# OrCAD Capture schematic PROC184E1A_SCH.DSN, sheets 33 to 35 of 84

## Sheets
33 37. SERDES CLOCK GENERATOR #2: size C; title: SERDES CLOCK GENERATOR #2; note: PROC184_SCH
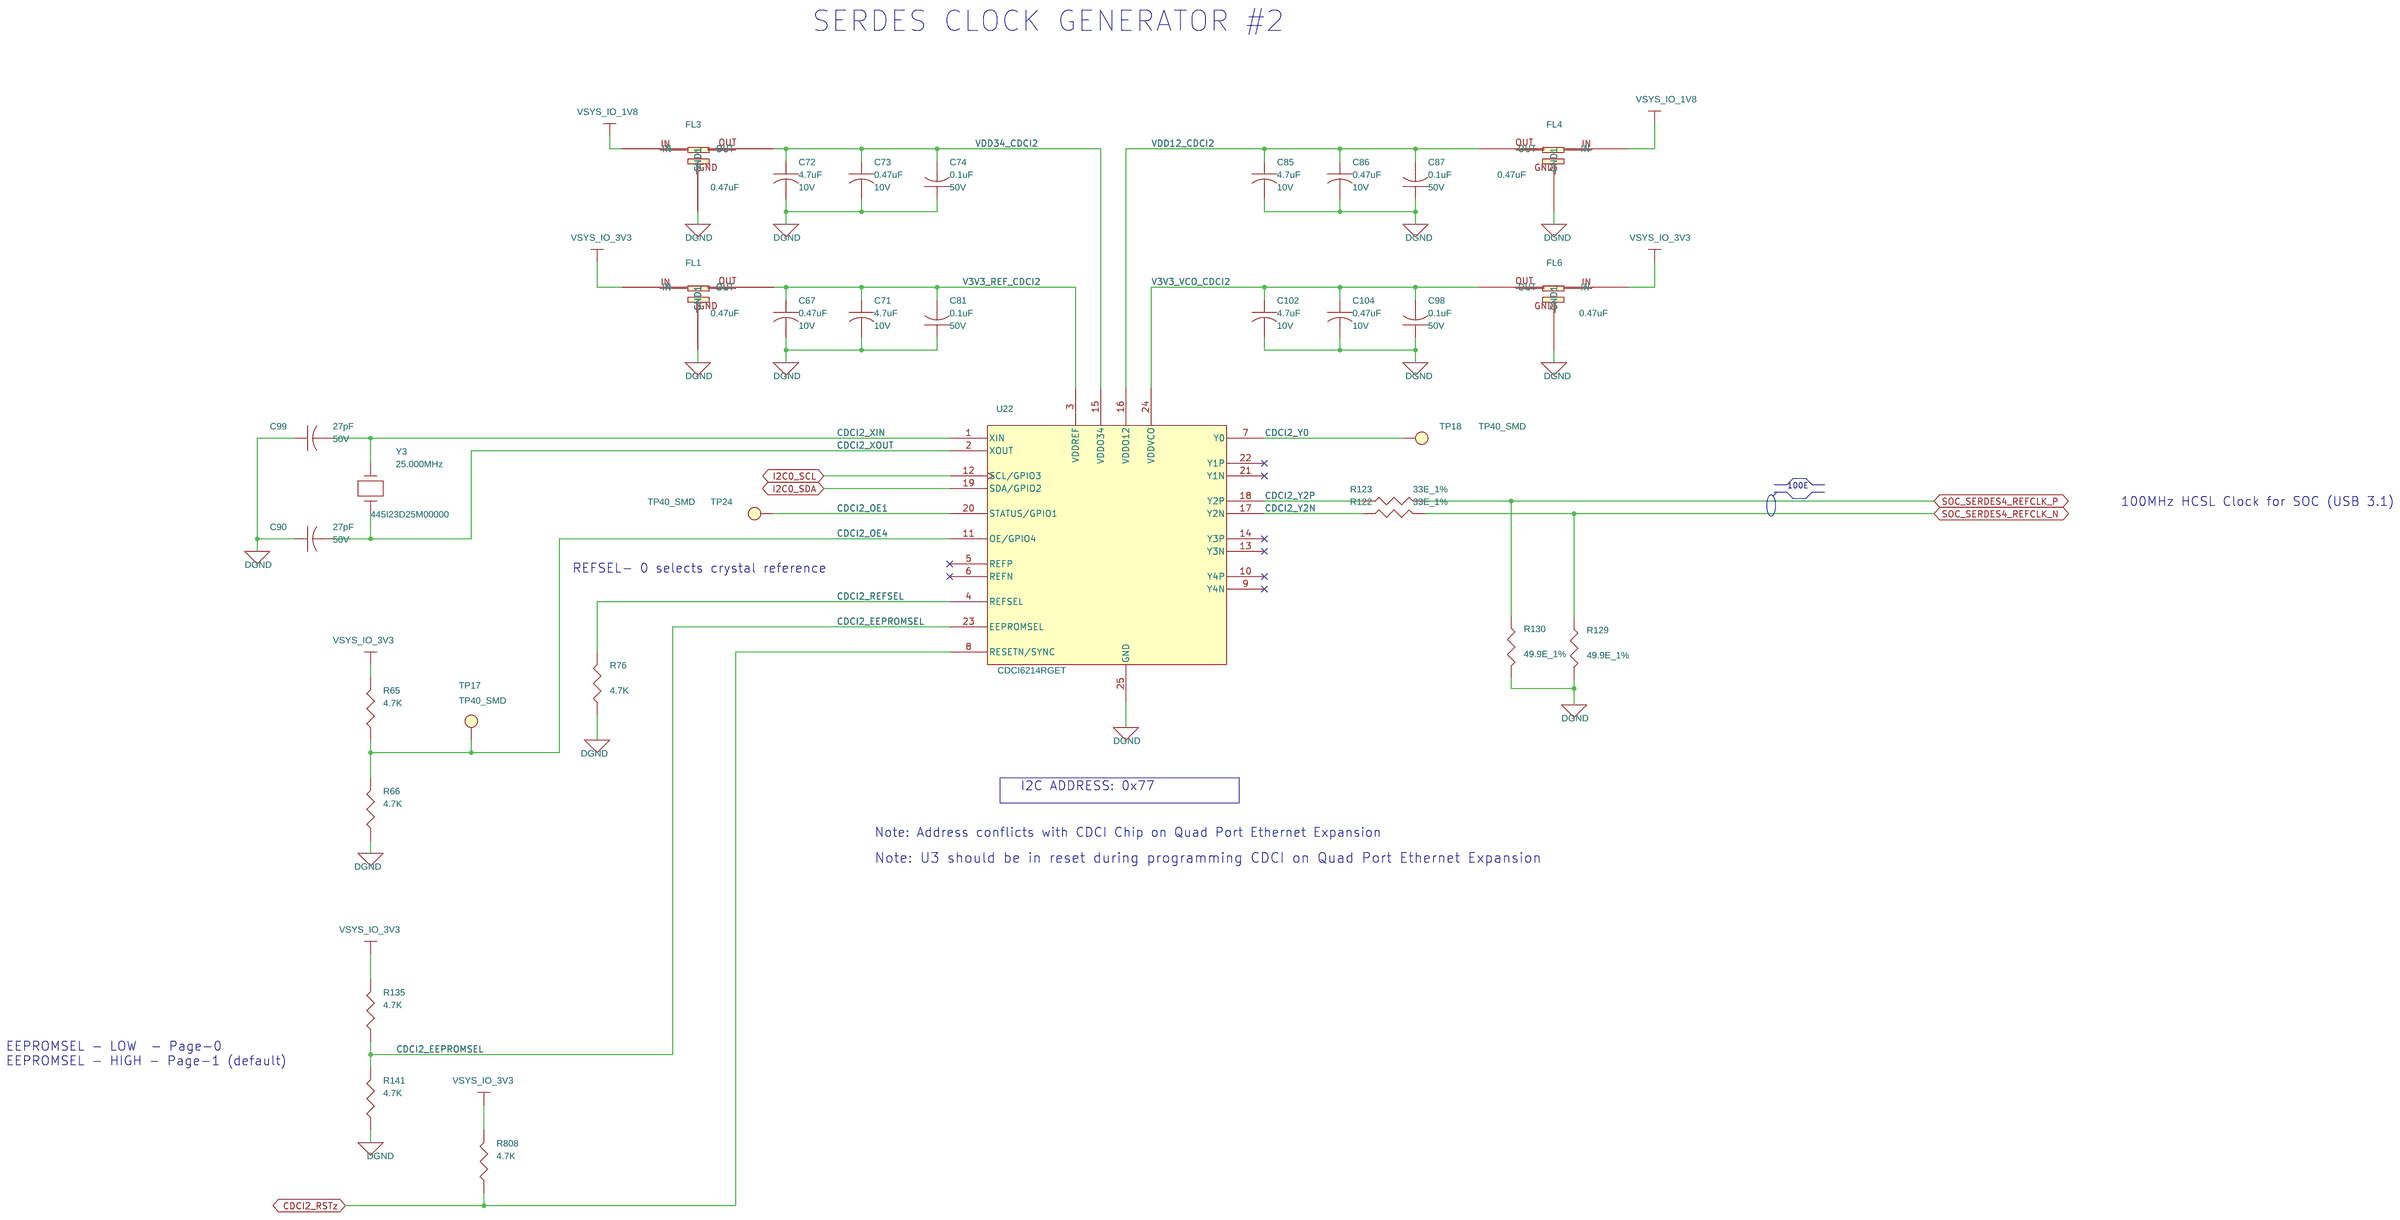
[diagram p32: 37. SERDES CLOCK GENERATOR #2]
34 38. PERIPHERAL CLOCK GENERATOR: size C; title: PERIPHERAL CLOCK GENERATOR; note: PROC184_SCH
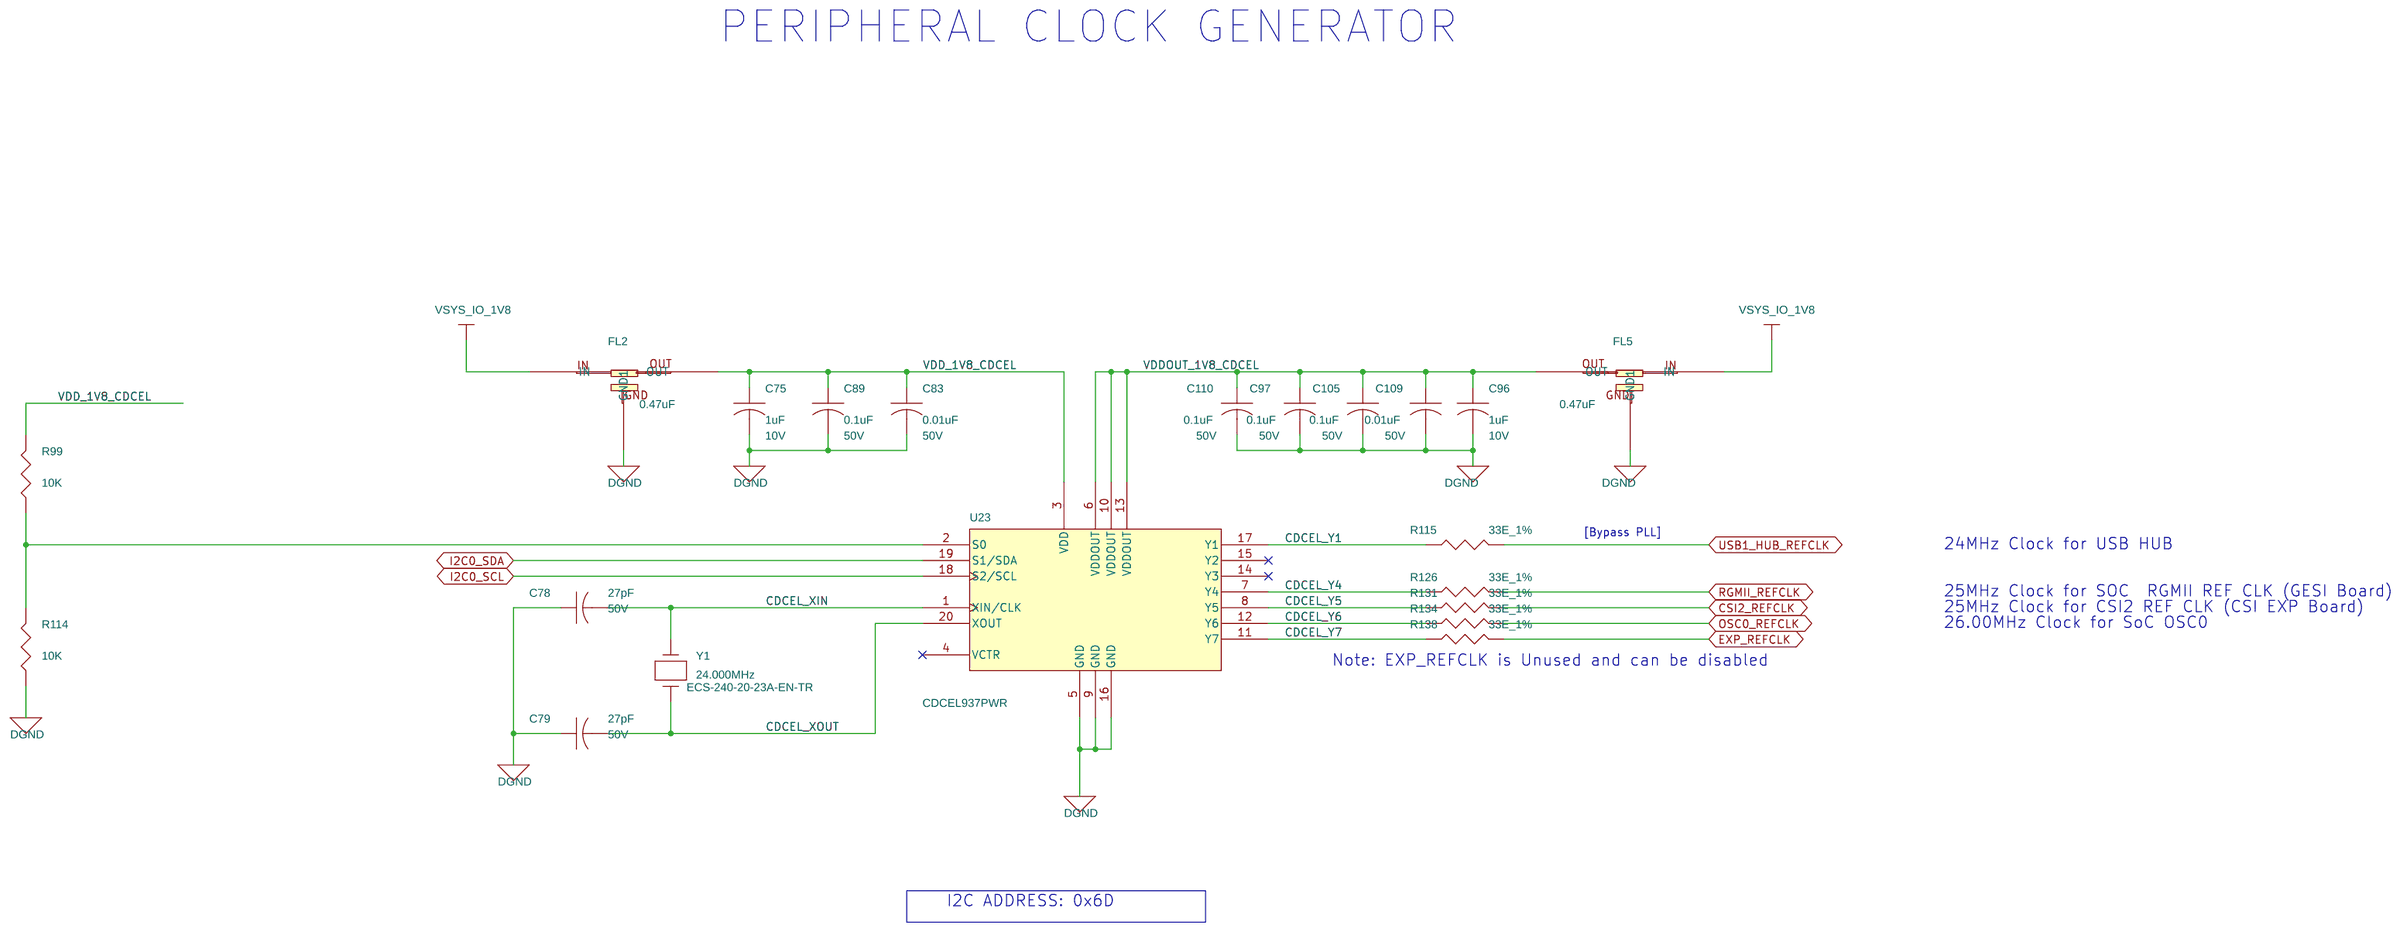
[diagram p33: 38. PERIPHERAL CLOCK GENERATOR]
35 39. RESET BUTTONs: size C; title: RESET BUTTONs; note: PROC184_SCH
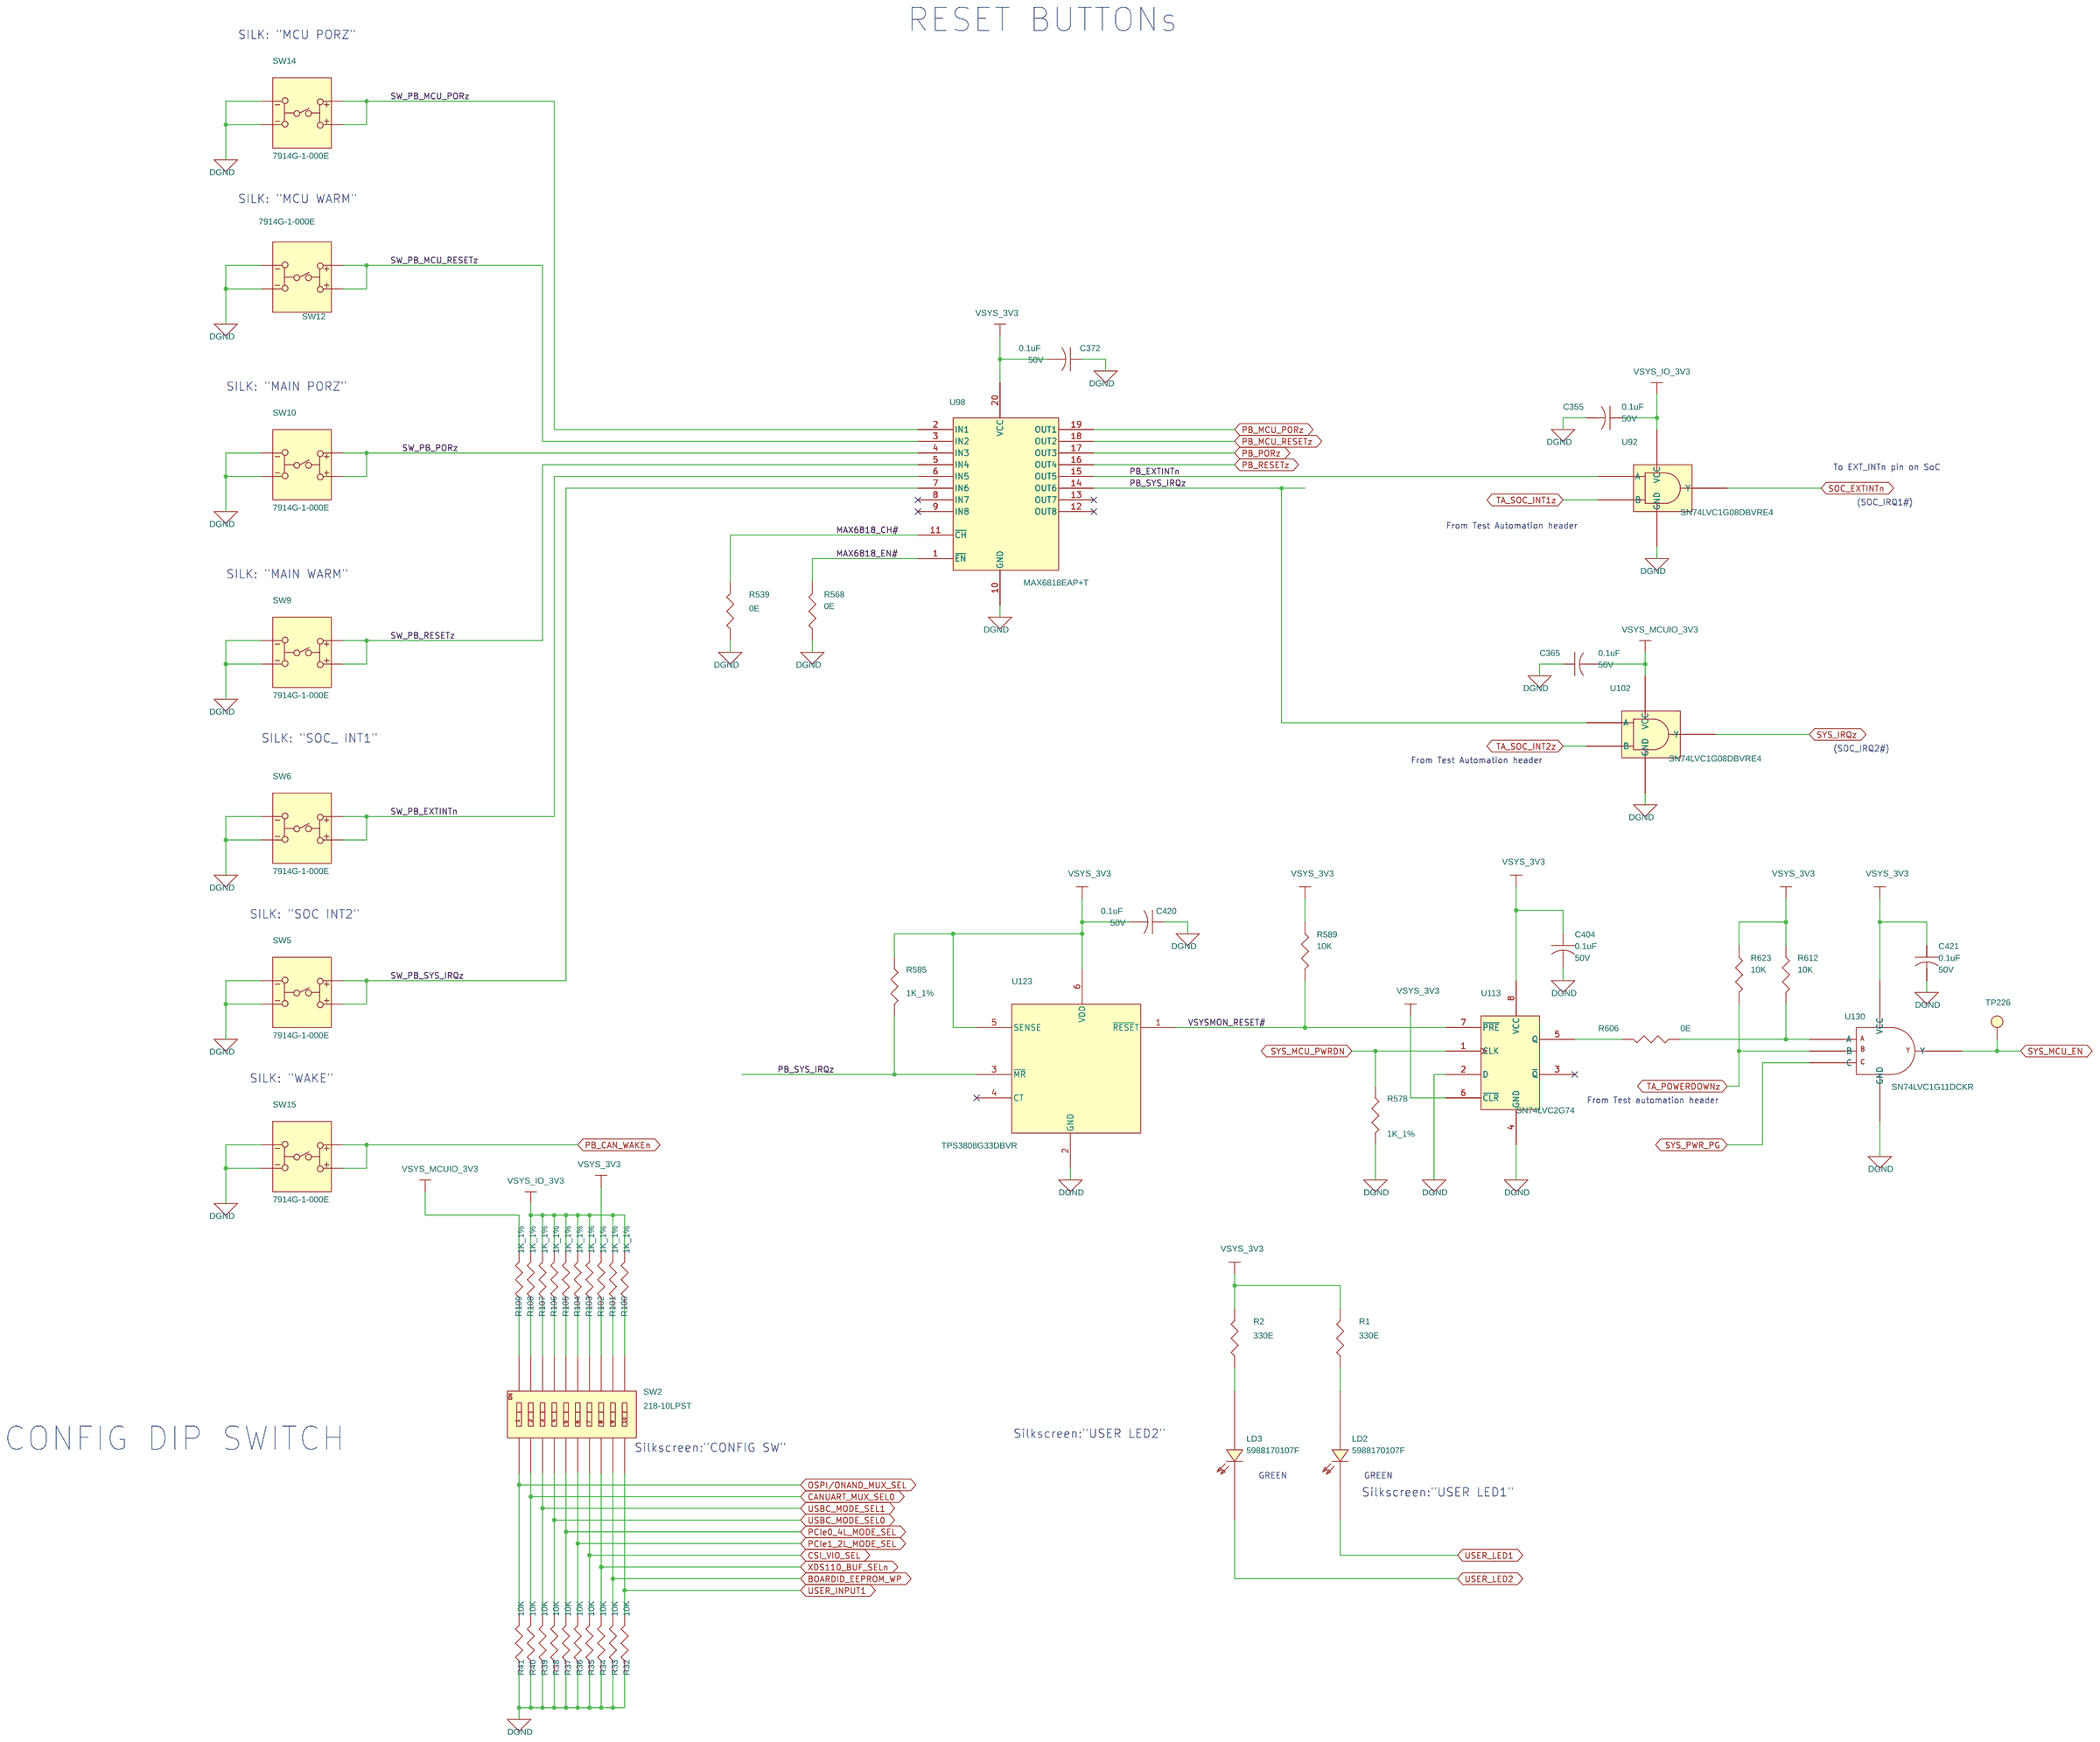
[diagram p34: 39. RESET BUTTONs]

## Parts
sheet 37. SERDES CLOCK GENERATOR #2
C67  0.47uF  [CAP0402_0-75]
C71  4.7uF  [CAP0402_0-75]
C72  4.7uF  [CAP0402_0-75]
C73  0.47uF  [CAP0402_0-75]
C74  0.1uF  [CAP0402_0-75]
C81  0.1uF  [CAP0402_0-75]
C85  4.7uF  [CAP0402_0-75]
C86  0.47uF  [CAP0402_0-75]
C87  0.1uF  [CAP0402_0-75]
C90  27pF  [CAP0402_0-75]
C98  0.1uF  [CAP0402_0-75]
C99  27pF  [CAP0402_0-75]
C102  4.7uF  [CAP0402_0-75]
C104  0.47uF  [CAP0402_0-75]
FL1  0.47uF  [EMIFIL_NFM21P_0805]
FL3  0.47uF  [EMIFIL_NFM21P_0805]
FL4  0.47uF  [EMIFIL_NFM21P_0805]
FL6  0.47uF  [EMIFIL_NFM21P_0805]
R65  4.7K  [RES0402_0-5]
R66  4.7K  [RES0402_0-5]
R76  4.7K  [RES0402_0-5]
R122  33E_1%  [RES0402_0-5]
R123  33E_1%  [RES0402_0-5]
R129  49.9E_1%  [RES0402_0-5]
R130  49.9E_1%  [RES0402_0-5]
R135  4.7K  [RES0402_0-5]
R141  4.7K  [RES0402_0-5]
R808  4.7K  [RES0402_0-5]
TP17  TP40_SMD  [TP40_SMD]
TP18  TP40_SMD  [TP40_SMD]
TP24  TP40_SMD  [TP40_SMD]
U22  CDCI6214RGET  [QFN24_19-68_160X160_1]
Y3  25.000MHz  [XTAL_ABM3_205X130_SMD_1-4]
sheet 38. PERIPHERAL CLOCK GENERATOR
C75  1uF  [CAP0402_0-75]
C78  27pF  [CAP0402_0-75]
C79  27pF  [CAP0402_0-75]
C83  0.01uF  [CAP0402_0-75]
C89  0.1uF  [CAP0402_0-75]
C96  1uF  [CAP0402_0-75]
C97  0.1uF  [CAP0402_0-75]
C105  0.1uF  [CAP0402_0-75]
C109  0.01uF  [CAP0402_0-75]
C110  0.1uF  [CAP0402_0-75]
FL2  0.47uF  [EMIFIL_NFM21P_0805]
FL5  0.47uF  [EMIFIL_NFM21P_0805]
R99  10K  [RES0402_0-5]
R114  10K  [RES0402_0-5]
R115  33E_1%  [RES0402_0-5]
R126  33E_1%  [RES0402_0-5]
R131  33E_1%  [RES0402_0-5]
R134  33E_1%  [RES0402_0-5]
R138  33E_1%  [RES0402_0-5]
U23  CDCEL937PWR  [TSSOP20_25-59_260X180_1-2]
Y1  24.000MHz  [XTAL_ECX-64AEN_240X150_SMD_1-1]
sheet 39. RESET BUTTONs
C355  0.1uF  [CAP0402_0-75]
C365  0.1uF  [CAP0402_0-75]
C372  0.1uF  [CAP0402_0-75]
C404  0.1uF  [CAP0402_0-75]
C420  0.1uF  [CAP0402_0-75]
C421  0.1uF  [CAP0402_0-75]
LD2  5988170107F  [LED_0805_0-7]
LD3  5988170107F  [LED_0805_0-7]
R1  330E  [RES0402_0-5]
R2  330E  [RES0402_0-5]
R32  10K  [RES0402_0-5]
R33  10K  [RES0402_0-5]
R34  10K  [RES0402_0-5]
R35  10K  [RES0402_0-5]
R36  10K  [RES0402_0-5]
R37  10K  [RES0402_0-5]
R38  10K  [RES0402_0-5]
R39  10K  [RES0402_0-5]
R40  10K  [RES0402_0-5]
R41  10K  [RES0402_0-5]
R100  1K_1%  [RES0402_0-5]
R101  1K_1%  [RES0402_0-5]
R102  1K_1%  [RES0402_0-5]
R103  1K_1%  [RES0402_0-5]
R104  1K_1%  [RES0402_0-5]
R105  1K_1%  [RES0402_0-5]
R106  1K_1%  [RES0402_0-5]
R107  1K_1%  [RES0402_0-5]
R108  1K_1%  [RES0402_0-5]
R109  1K_1%  [RES0402_0-5]
R539  0E  [RES0402_0-5]
R568  0E  [RES0402_0-5]
R578  1K_1%  [RES0402_0-5]
R585  1K_1%  [RES0402_0-5]
R589  10K  [RES0402_0-5]
R606  0E  [RES0402_0-5]
R612  10K  [RES0402_0-5]
R623  10K  [RES0402_0-5]
SW2  218-10LPST  [SW10_50_550X230_SMD]
SW5  7914G-1-000E  [SW4_100X216_200X200_SMD_4-2]
SW6  7914G-1-000E  [SW4_100X216_200X200_SMD_4-2]
SW9  7914G-1-000E  [SW4_100X216_200X200_SMD_4-2]
SW10  7914G-1-000E  [SW4_100X216_200X200_SMD_4-2]
SW12  7914G-1-000E  [SW4_100X216_200X200_SMD_4-2]
SW14  7914G-1-000E  [SW4_100X216_200X200_SMD_4-2]
SW15  7914G-1-000E  [SW4_100X216_200X200_SMD_4-2]
TP226  TP40_SMD  [TP40_SMD]
U92  SN74LVC1G08DBVRE4  [SOT23-5]
U98  MAX6818EAP+T  [SSOP20_25-59_295X220_2]
U102  SN74LVC1G08DBVRE4  [SOT23-5]
U113  SN74LVC2G74  [VSSOP8_19-68_85X95]
U123  TPS3808G33DBVR  [SOT23-6_1-5]
U130  SN74LVC1G11DCKR  [SC70-6]

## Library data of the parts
C67 C73 C86 C104 = CAP: CAP CERAMIC 0.47uF 10V 10% X7S AUTO 0402; Automotive Alternate_mfr_name: MURATA; Automotive Alternate_mfr_part_number: GCM155C71A474KE36D; Chkd/date: MANIRAJA/280918; Crtd /date: ALVY/280918; Custom_Duty: 15%; Customs_HS_Code: 85322990; Direct Alternate_mfr_name: MURATA; Direct Alternate_mfr_part_number: GCM155C71A474KE36D; Distributor_name: DIGIKEY; Distributor_part_number: 490-14427-1-ND; Footprint Path: Y:\MIS_DATABASE\Library\ALTIUM_TOOL\PCB_FOOTPRINTS\Altium_Footprint_Lib.PcbLib; Height: 0.60MM; Library Path: Y:\MIS_DATABASE\Library\ALTIUM_TOOL\SCHEMATICS_PARTS\MS_DISCRETE_Library.schlib; Manufacturer: MURATA; Mfr_name: MURATA; Mfr_part_number: GCM155C71A474KE36D; Mistral Part No: 120018090057-R; Package: 0402; Part_type: CAPACITORS\CERAMIC; Project: TI_J7_SVB-DUT; RoHS: RoHS; Temperature: -55°C+125°C; Tolerance: 10%; Voltage: 10V; Wattage: NA; Weight: 6mg; Datasheet: Y:\MIS_DATABASE\DATASHEETS\CAPACITORS\GCM155C71A474KE36D.PDF
C71 C72 C85 C102 = CAP: CAP CERAMIC 4.7uF 10V 20% X5R 0402; Automotive Alternate_mfr_name: MURATA; Automotive Alternate_mfr_part_number: GRT155R61A475ME13D; Chkd/date: VASANTHA/061216; Crtd /date: CHAITHANYA/070612; Custom_Duty: 15%; Customs_HS_Code: 85322990; Direct Alternate_mfr_name: MURATA; Direct Alternate_mfr_part_number: GRM155R61A475MEAAD; Distributor_name: DIGIKEY; Distributor_part_number: 445-8023-1-ND; Footprint Path: Y:\MIS_DATABASE\Library\ALTIUM_TOOL\PCB_FOOTPRINTS\Altium_Footprint_Lib.PcbLib; Height: 0.55MM; Library Path: Y:\MIS_DATABASE\Library\ALTIUM_TOOL\SCHEMATICS_PARTS\MS_DISCRETE_Library.schlib; Manufacturer: TDK CORPORATION; Mfr_name: TDK CORPORATION; Mfr_part_number: C1005X5R1A475M; Mistral Part No: 120012060002-R; Package: 0402; Part_type: CAPACITORS\CERAMIC; Project: IRIS; RoHS: RoHS; Temperature: -55°C+85°C; Tolerance: 20%; Voltage: 10V; Wattage: NA; Weight: 0.65mg; Datasheet: Y:\MIS_DATABASE\DATASHEETS\CAPACITORS\TDK-C-SER_JUL17.PDF
C74 C81 C87 C89 C97 C98 C105 C110 C355 C365 C372 C404 C420 C421 = CAP: CAP CERAMIC 0.1uF 50V 10% X7R 0402; Automotive Alternate_mfr_name: TDK; Automotive Alternate_mfr_part_number: CGA2B3X7R1H104K050BB; Chkd/date: MANIRAJA/261020; Crtd /date: ALVY/211020; Custom_Duty: 15%; Customs_HS_Code: 85322990; Direct Alternate_mfr_name: TDK; Direct Alternate_mfr_part_number: C1005X7R1H104K050BE; Distributor_name: DIGIKEY; Distributor_part_number: 490-10700-1-ND; Footprint Path: Y:\MIS_DATABASE\Library\ALTIUM_TOOL\PCB_FOOTPRINTS\Altium_Footprint_Lib.PcbLib; Height: 0.55MM; Library Path: Y:\MIS_DATABASE\Library\ALTIUM_TOOL\SCHEMATICS_PARTS\MS_DISCRETE_Library.schlib; Manufacturer: MURATA; Mfr_name: MURATA; Mfr_part_number: GRM155R71H104KE14D; Mistral Part No: 120011100014-R; Package: 0402; Part_type: CAPACITORS\CERAMIC; Project: J7_CP; RoHS: RoHS; Temperature: -55°C+125°C; Tolerance: 10%; Voltage: 50V; Wattage: NA; Weight: 3.1mg; Datasheet: Y:\MIS_DATABASE\DATASHEETS\CAPACITORS\GRM155R71H104KE14.PDF
C90 C99 = CAP: CAP CERAMIC 27pF 50V 5% C0G(NP0) 0402; Assembly_Instruction: DNI; Automotive Alternate_mfr_name: TDK; Automotive Alternate_mfr_part_number: CGA2B2C0G1H270J050BA; Chkd/date: MAZHAR/241208; Crtd /date: GEETHA/090606; Custom_Duty: 15%; Customs_HS_Code: 85322990; Direct Alternate_mfr_name: SAMSUNG; Direct Alternate_mfr_part_number: CL05C270JB5NNNC; Distributor_name: DIGIKEY; Distributor_part_number: 311-1019-1-ND; Footprint Path: Y:\MIS_DATABASE\Library\ALTIUM_TOOL\PCB_FOOTPRINTS\Altium_Footprint_Lib.PcbLib; Height: 0.55MM; Library Path: Y:\MIS_DATABASE\Library\ALTIUM_TOOL\SCHEMATICS_PARTS\MS_DISCRETE_Library.schlib; Manufacturer: YAGEO AMERICA; Mfr_name: YAGEO AMERICA; Mfr_part_number: CC0402JRNPO9BN270; Mistral Part No: 120014100024-R; Package: 0402; Part_type: CAPACITORS\CERAMIC; Project: PNAV; RoHS: RoHS; Temperature: -55°C+125°C; Tolerance: 5%; Voltage: 50V; Wattage: NA; Weight: 0.65mg; Datasheet: Y:\MIS_DATABASE\DATASHEETS\CAPACITORS\YACC-NPO.PDF
FL1-FL6 = CAP_FILTER: PASSIVE FILTER EMI 0.47uF 0805; Chkd/date: RAGESH/121010; Crtd /date: MUDDU/010210; Custom_Duty: 24%; Customs_HS_Code: 85437099; Distributor_name: DIGIKEY; Distributor_part_number: 490-2537-1-ND; Height: 0.95MM; Manufacturer: MURATA; Mfr_name: MURATA; Mfr_part_number: NFM21PC474R1C3D; Mistral Part No: 130010010009; Package: 0805; Part_type: FILTER; Project: KOPIN_MODULS; Temperature: -55°C+125°C; Weight: NA; Datasheet: Y:\MIS_DATABASE\DATASHEETS\ICS\MISC\NFM21P.PDF
R65 R76 R135 R808 = RESISTOR: RES 4.7K 1/16W 5% 0402; Chkd/date: VASANTHA/130516; Crtd /date: VASANTHA/130516; Custom_Duty: 15%; Customs_HS_Code: 85332119; Distributor_name: DIGIKEY; Distributor_part_number: 311-4.7KJRCT-ND; Footprint Path: Y:\MIS_DATABASE\Library\ALTIUM_TOOL\PCB_FOOTPRINTS\Altium_Footprint_Lib.PcbLib; Height: 0.40MM; Library Path: Y:\MIS_DATABASE\Library\ALTIUM_TOOL\SCHEMATICS_PARTS\MS_DISCRETE_Library.schlib; Manufacturer: YAGEO AMERICA; Mfr_name: YAGEO AMERICA; Mfr_part_number: RC0402JR-074K7L; Mistral Part No: 110011060001-R; Package: 0402; Part_type: RESISTORS\FIXED; Project: TMDXCSK368; RoHS: RoHS; Temperature: -55°C+155°C; Tolerance: 5%; Voltage: NA; Wattage: 1/16W; Weight: 0.65mg; Datasheet: Y:\MIS_DATABASE\DATASHEETS\RESISTORS\RCXXXXL-SER_MAR18.PDF
R66 R141 = RESISTOR: RES 4.7K 1/16W 5% 0402; Assembly_Instruction: DNI; Chkd/date: VASANTHA/130516; Crtd /date: VASANTHA/130516; Custom_Duty: 15%; Customs_HS_Code: 85332119; Distributor_name: DIGIKEY; Distributor_part_number: 311-4.7KJRCT-ND; Footprint Path: Y:\MIS_DATABASE\Library\ALTIUM_TOOL\PCB_FOOTPRINTS\Altium_Footprint_Lib.PcbLib; Height: 0.40MM; Library Path: Y:\MIS_DATABASE\Library\ALTIUM_TOOL\SCHEMATICS_PARTS\MS_DISCRETE_Library.schlib; Manufacturer: YAGEO AMERICA; Mfr_name: YAGEO AMERICA; Mfr_part_number: RC0402JR-074K7L; Mistral Part No: 110011060001-R; Package: 0402; Part_type: RESISTORS\FIXED; Project: TMDXCSK368; RoHS: RoHS; Temperature: -55°C+155°C; Tolerance: 5%; Voltage: NA; Wattage: 1/16W; Weight: 0.65mg; Datasheet: Y:\MIS_DATABASE\DATASHEETS\RESISTORS\RCXXXXL-SER_MAR18.PDF
R115 R122 R123 R126 R131 R134 R138 = RESISTOR: RES 33E 1/10W 1% 0402; Chkd/date: VASANTHA/061216; Crtd /date: JEBRAN/171114; Custom_Duty: 15%; Customs_HS_Code: 85332119; Distributor_name: DIGIKEY; Distributor_part_number: P33.0LCT-ND; Footprint Path: Y:\MIS_DATABASE\Library\ALTIUM_TOOL\PCB_FOOTPRINTS\Altium_Footprint_Lib.PcbLib; Height: 0.40MM; Library Path: Y:\MIS_DATABASE\Library\ALTIUM_TOOL\SCHEMATICS_PARTS\MS_DISCRETE_Library.schlib; Manufacturer: PANASONIC-ECG; Mfr_name: PANASONIC-ECG; Mfr_part_number: ERJ-2RKF33R0X; Mistral Part No: 110014110006-R; Package: 0402; Part_type: RESISTORS\FIXED; Project: ZK BIOMETRIC; RoHS: RoHS; Temperature: -55°C+155°C; Tolerance: 1%; Voltage: NA; Wattage: 1/10W; Weight: 0.8mg; Datasheet: Y:\MIS_DATABASE\DATASHEETS\RESISTORS\PAN-ERJSER_NOV17.PDF
R129 R130 = RESISTOR: RES 49.9E 1/10W 1% 0402; Chkd/date: VASANTHA/201216; Crtd /date: MAZHAR/201005; Custom_Duty: 15%; Customs_HS_Code: 85332119; Distributor_name: DIGIKEY; Distributor_part_number: P49.9LCT-ND; Footprint Path: Y:\MIS_DATABASE\Library\ALTIUM_TOOL\PCB_FOOTPRINTS\Altium_Footprint_Lib.PcbLib; Height: 0.40MM; Library Path: Y:\MIS_DATABASE\Library\ALTIUM_TOOL\SCHEMATICS_PARTS\MS_DISCRETE_Library.schlib; Manufacturer: PANASONIC-ECG; Mfr_name: PANASONIC-ECG; Mfr_part_number: ERJ-2RKF49R9X; Mistral Part No: 110009030897-R; Package: 0402; Part_type: RESISTORS\FIXED; Project: RED EYE; RoHS: RoHS; Temperature: -55°C+155°C; Tolerance: 1%; Voltage: NA; Wattage: 1/10W; Weight: 0.8mg; Datasheet: Y:\MIS_DATABASE\DATASHEETS\RESISTORS\PAN-ERJSER_NOV17.PDF
TP17 TP18 TP24 TP226 = TESTPOINT: TESTPOINT CIR 40 SMD; Chkd/date: MAZHAR/190505; Crtd /date: MAZHAR/190505; Distributor_name: NA; Distributor_part_number: NA; Footprint Path: Y:\MIS_DATABASE\Library\ALTIUM_TOOL\PCB_FOOTPRINTS\Altium_Footprint_Lib.PcbLib; Height: NA; Library Path: Y:\MIS_DATABASE\Library\ALTIUM_TOOL\SCHEMATICS_PARTS\MS_DISCRETE_Library.schlib; MECHANICAL 3D STEP FILE: NA; Manufacturer: LOCAL; Mfr_name: LOCAL; Mistral Part No: 130009030933; Package: SMD; Project: RAINIER-3; RoHS: NA; Temperature: NA; Tolerance: NA; Voltage: NA; Wattage: NA; Weight: NA; Datasheet: NA
U22 = CDCI6214RGET_VQFN24: IC PCIE GEN4 CLOCK GENERATOR WITH PROGRAMMABLE O/P AND EEPROM VQFN24; Chkd/date: MANIRAJA/051017; Crtd /date: MANIRAJA/051017; Custom_Duty: 15%; Customs_HS_Code: 85423100; Distributor_name: NA; Distributor_part_number: NA; Height: 1.00MM; Manufacturer: TEXAS INSTRUMENTS; Mfr_name: TEXAS INSTRUMENTS; Mistral Part No: 141017100002-R; Package: VQFN24; Part_type: ICS\DIGITAL\PERIPHERAL; Project: TI_SVB_MAXWELL_DUT; RoHS: RoHS; Temperature: -40°C+85°C; Tolerance: NA; Voltage: NA; Wattage: NA; Weight: NA; Datasheet: Y:\MIS_DATABASE\DATASHEETS\ICS\DIGITAL\PERIPHERAL\CDCI6214.PDF
Y3 = CRY: CRY 25.000MHz 18pF SMD; Chkd/date: VASANTHA/110316; Crtd /date: JEBRAN/090216; Custom_Duty: 24%; Customs_HS_Code: 85439000; Distributor_name: DIGIKEY; Distributor_part_number: CTX1175CT-ND; Footprint Path: Y:\MIS_DATABASE\Library\ALTIUM_TOOL\PCB_FOOTPRINTS\Altium_Footprint_Lib.PcbLib; Height: 1.35MM; Library Path: Y:\MIS_DATABASE\Library\ALTIUM_TOOL\SCHEMATICS_PARTS\MS_DISCRETE_Library.schlib; Manufacturer: CTS; Mfr_name: CTS; Mfr_part_number: 445I23D25M00000; Mistral Part No: 130016020016-R; Package: SMD; Part_type: CRYSTAL; Project: PDI_MINIPCB; RoHS: RoHS; Temperature: -40°C+85°C; Tolerance: NA; Voltage: NA; Wattage: NA; Weight: 50mg; Datasheet: Y:\MIS_DATABASE\DATASHEETS\MISC\CRY_OSC\445.PDF
C75 C96 = CAP: CAP CERAMIC 1uF 10V 10% X7S AUTO 0402; Automotive Alternate_mfr_name: TAIYO YUDEN; Automotive Alternate_mfr_part_number: EMK105BJ105KVHF; Chkd/date: MANIRAJA/100918; Crtd /date: ALVY/100918; Custom_Duty: 15%; Customs_HS_Code: 85322990; Direct Alternate_mfr_name: YAGEO AMERICA; Direct Alternate_mfr_part_number: CC0402KRX5R7BB105; Distributor_name: DIGIKEY; Distributor_part_number: 490-13409-1-ND; Footprint Path: Y:\MIS_DATABASE\Library\ALTIUM_TOOL\PCB_FOOTPRINTS\Altium_Footprint_Lib.PcbLib; Height: 0.70MM; Library Path: Y:\MIS_DATABASE\Library\ALTIUM_TOOL\SCHEMATICS_PARTS\MS_DISCRETE_Library.schlib; Manufacturer: TDK CORPORATION; Mfr_name: MURATA; Mfr_part_number: GCM155C71A105KE38D; Mistral Part No: 120018090021-R; Package: 0402; Part_type: CAPACITORS\CERAMIC; Project: SMART-M_SCRIPTALK_PB; RoHS: RoHS; Temperature: -55°C+125°C; Tolerance: 10%; Voltage: 10V; Wattage: NA; Weight: 6mg; Datasheet: Y:\MIS_DATABASE\DATASHEETS\CAPACITORS\MURATA-GCM-SER.PDF
C78 C79 = CAP: CAP CERAMIC 27pF 50V 5% C0G(NP0) 0402; Automotive Alternate_mfr_name: TDK; Automotive Alternate_mfr_part_number: CGA2B2C0G1H270J050BA; Chkd/date: MAZHAR/241208; Crtd /date: GEETHA/090606; Custom_Duty: 15%; Customs_HS_Code: 85322990; Direct Alternate_mfr_name: SAMSUNG; Direct Alternate_mfr_part_number: CL05C270JB5NNNC; Distributor_name: DIGIKEY; Distributor_part_number: 311-1019-1-ND; Footprint Path: Y:\MIS_DATABASE\Library\ALTIUM_TOOL\PCB_FOOTPRINTS\Altium_Footprint_Lib.PcbLib; Height: 0.55MM; Library Path: Y:\MIS_DATABASE\Library\ALTIUM_TOOL\SCHEMATICS_PARTS\MS_DISCRETE_Library.schlib; Manufacturer: YAGEO AMERICA; Mfr_name: YAGEO AMERICA; Mfr_part_number: CC0402JRNPO9BN270; Mistral Part No: 120014100024-R; Package: 0402; Part_type: CAPACITORS\CERAMIC; Project: PNAV; RoHS: RoHS; Temperature: -55°C+125°C; Tolerance: 5%; Voltage: 50V; Wattage: NA; Weight: 0.65mg; Datasheet: Y:\MIS_DATABASE\DATASHEETS\CAPACITORS\YACC-NPO.PDF
C83 C109 = CAP: CAP CERAMIC 0.01uF 50V 10% X7R 0402; Automotive Alternate_mfr_name: TDK; Automotive Alternate_mfr_part_number: CGA2B2X7R1E103K050BA; Chkd/date: MANIRAJA/280319; Crtd /date: MANIRAJA/280319; Custom_Duty: 15%; Customs_HS_Code: 85322990; Direct Alternate_mfr_name: YAGEO AMERICA; Direct Alternate_mfr_part_number: CC0402KRX7R8BB103; Distributor_name: DIGIKEY; Distributor_part_number: 490-4516-1-ND; Footprint Path: Y:\MIS_DATABASE\Library\ALTIUM_TOOL\PCB_FOOTPRINTS\Altium_Footprint_Lib.PcbLib; Height: 0.55MM; Library Path: Y:\MIS_DATABASE\Library\ALTIUM_TOOL\SCHEMATICS_PARTS\MS_DISCRETE_Library.schlib; Manufacturer: MURATA; Mfr_name: MURATA; Mfr_part_number: GRM155R71H103KA88D; Mistral Part No: 120009030025-R; Package: 0402; Part_type: CAPACITORS\CERAMIC; Project: G4_SVGA; RoHS: RoHS; Temperature: -55°C+125°C; Tolerance: 10%; Voltage: 50V; Wattage: NA; Weight: 0.65mg; Datasheet: Y:\MIS_DATABASE\DATASHEETS\CAPACITORS\GRM155R71H103KA88D.PDF
R32-R41 R99 R589 R612 R623 = RESISTOR: RES 10K 1/16W 5% 0402; Chkd/date: VASANTHA/061216; Crtd /date: MAZHAR/230805; Custom_Duty: 15%; Customs_HS_Code: 85332119; Distributor_name: DIGIKEY; Distributor_part_number: 311-10KJRCT-ND; Footprint Path: Y:\MIS_DATABASE\Library\ALTIUM_TOOL\PCB_FOOTPRINTS\Altium_Footprint_Lib.PcbLib; Height: 0.40MM; Library Path: Y:\MIS_DATABASE\Library\ALTIUM_TOOL\SCHEMATICS_PARTS\MS_DISCRETE_Library.schlib; Manufacturer: YAGEO AMERICA; Mfr_name: YAGEO AMERICA; Mfr_part_number: RC0402JR-0710KL; Mistral Part No: 110011060021-R; Package: 0402; Part_type: RESISTORS\FIXED; Project: HSE; RoHS: RoHS; Temperature: -55°C+155°C; Tolerance: 5%; Voltage: NA; Wattage: 1/16W; Weight: 0.65mg; Datasheet: Y:\MIS_DATABASE\DATASHEETS\RESISTORS\RCXXXXL-SER_MAR18.PDF
R114 = RESISTOR: RES 10K 1/16W 5% 0402; Assembly_Instruction: DNI; Chkd/date: VASANTHA/061216; Crtd /date: MAZHAR/230805; Custom_Duty: 15%; Customs_HS_Code: 85332119; Distributor_name: DIGIKEY; Distributor_part_number: 311-10KJRCT-ND; Footprint Path: Y:\MIS_DATABASE\Library\ALTIUM_TOOL\PCB_FOOTPRINTS\Altium_Footprint_Lib.PcbLib; Height: 0.40MM; Library Path: Y:\MIS_DATABASE\Library\ALTIUM_TOOL\SCHEMATICS_PARTS\MS_DISCRETE_Library.schlib; Manufacturer: YAGEO AMERICA; Mfr_name: YAGEO AMERICA; Mfr_part_number: RC0402JR-0710KL; Mistral Part No: 110011060021-R; Package: 0402; Part_type: RESISTORS\FIXED; Project: HSE; RoHS: RoHS; Temperature: -55°C+155°C; Tolerance: 5%; Voltage: NA; Wattage: 1/16W; Weight: 0.65mg; Datasheet: Y:\MIS_DATABASE\DATASHEETS\RESISTORS\RCXXXXL-SER_MAR18.PDF
U23 = CDCEL937-Q1_TSSOP20: IC 3-PLL LVCMOS CLOCK GENERATOR WITH SSC SUPPORT TSSOP20; Automotive Alternate_mfr_name: TEXAS INSTRUMENTS; Automotive Alternate_mfr_part_number: CDCE937QPWRQ1; Chkd/date: MANIRAJA/161018; Crtd /date: ALVY/161018; Custom_Duty: 15%; Customs_HS_Code: 85423100; Distributor_name: DIGIKEY; Distributor_part_number: CDCEL937PWR-ND; Footprint Path: Y:\MIS_DATABASE\Library\ALTIUM_TOOL\PCB_FOOTPRINTS\Altium_Footprint_Lib.PcbLib; Height: 1.20MM; Library Path: Y:\MIS_DATABASE\Library\ALTIUM_TOOL\SCHEMATICS_PARTS\MS_COMBINATIONAL_Library.schlib; Manufacturer: TEXAS INSTRUMENTS; Mfr_name: TEXAS INSTRUMENTS; Mistral Part No: 141018100015-R; Package: TSSOP20; Part_type: ICS\DIGITAL\COMBINATIONAL; Project: TI_J7ES_EVM_CP; RoHS: RoHS; Temperature: -40°C+85°C; Tolerance: NA; Voltage: NA; Wattage: NA; Weight: 77mg; Datasheet: Y:\MIS_DATABASE\DATASHEETS\ICS\DIGITAL\COMBINATIONAL\CDCEL937.PDF
Y1 = CRY: CRY 24.000MHz 20pF SMD; Chkd/date: MANIRAJA/220818; Crtd /date: CHAITHANYA/171111; Custom_Duty: 24%; Customs_HS_Code: 85439000; Distributor_name: DIGIKEY; Distributor_part_number: XC990CT-ND; Footprint Path: Y:\MIS_DATABASE\Library\ALTIUM_TOOL\PCB_FOOTPRINTS\Altium_Footprint_Lib.PcbLib; Height: 1.10MM; Library Path: Y:\MIS_DATABASE\Library\ALTIUM_TOOL\SCHEMATICS_PARTS\MS_DISCRETE_Library.schlib; Manufacturer: ECS INC; Mfr_name: ECS INC; Mfr_part_number: ECS-240-20-23A-EN-TR; Mistral Part No: 130011110044-R; Package: SMD; Part_type: CRYSTAL; Project: ACRO_DM3730; RoHS: RoHS; Temperature: -40°C+85°C; Tolerance: NA; Voltage: NA; Wattage: NA; Weight: 60mg; Datasheet: Y:\MIS_DATABASE\DATASHEETS\MISC\CRY_OSC\ECX-64XEN.PDF
LD2 LD3 = LED_598-8170-107F: LED ALINGAP GREEN CLEAR 0805; Chkd/date: MANIRAJA/230817; Crtd /date: SARANYA/070514; Custom_Duty: 24%; Customs_HS_Code: 85437099; Distributor_name: DIGIKEY; Distributor_part_number: 350-2044-1-ND; Footprint Path: Y:\MIS_DATABASE\Library\ALTIUM_TOOL\PCB_FOOTPRINTS\Altium_Footprint_Lib.PcbLib; Height: 0.70MM; Manufacturer: DIALIGHT; Mfr_name: DIALIGHT; Mistral Part No: 130014050065-R; Package: 0805; Part_type: OPTO\LED; Project: AEGIS GP BETA2; RoHS: RoHS; Temperature: -30°C+85°C; Tolerance: NA; Voltage: NA; Wattage: NA; Weight: NA; Datasheet: Y:\MIS_DATABASE\DATASHEETS\DISCRETES\LEDS\598-SER.PDF
R1 R2 = RESISTOR: RES 330E 1/10W 5% 0402; Chkd/date: VASANTHA/281216; Crtd /date: USMAN/090309; Custom_Duty: 15%; Customs_HS_Code: 85332119; Distributor_name: DIGIKEY; Distributor_part_number: P330JCT-ND; Footprint Path: Y:\MIS_DATABASE\Library\ALTIUM_TOOL\PCB_FOOTPRINTS\Altium_Footprint_Lib.PcbLib; Height: 0.40MM; Library Path: Y:\MIS_DATABASE\Library\ALTIUM_TOOL\SCHEMATICS_PARTS\MS_DISCRETE_Library.schlib; Manufacturer: PANASONIC-ECG; Mfr_name: PANASONIC-ECG; Mfr_part_number: ERJ-2GEJ331X; Mistral Part No: 110009031217-R; Package: 0402; Part_type: RESISTORS\FIXED; Project: PC104-SBC; RoHS: RoHS; Temperature: -55°C+155°C; Tolerance: 5%; Voltage: NA; Wattage: 1/10W; Weight: 0.8mg; Datasheet: Y:\MIS_DATABASE\DATASHEETS\RESISTORS\PAN-ERJSER_NOV17.PDF
R100-R109 R578 R585 = RESISTOR: RES 1K 1/10W 1% 0402; Chkd/date: VASANTHA/281216; Crtd /date: MAZHAR/150506; Custom_Duty: 15%; Customs_HS_Code: 85332119; Distributor_name: DIGIKEY; Distributor_part_number: P1.00KLCT-ND; Footprint Path: Y:\MIS_DATABASE\Library\ALTIUM_TOOL\PCB_FOOTPRINTS\Altium_Footprint_Lib.PcbLib; Height: 0.40MM; Library Path: Y:\MIS_DATABASE\Library\ALTIUM_TOOL\SCHEMATICS_PARTS\MS_DISCRETE_Library.schlib; Manufacturer: PANASONIC-ECG; Mfr_name: PANASONIC-ECG; Mfr_part_number: ERJ-2RKF1001X; Mistral Part No: 110009030411-R; Package: 0402; Part_type: RESISTORS\FIXED; Project: VOCERA; RoHS: RoHS; Temperature: -55°C+155°C; Tolerance: 1%; Voltage: NA; Wattage: 1/10W; Weight: 0.8mg; Datasheet: Y:\MIS_DATABASE\DATASHEETS\RESISTORS\PAN-ERJSER_NOV17.PDF
R539 = RESISTOR: RES 0E 1/10W JUMPER 0402; Assembly_Instruction: DNI; Chkd/date: VASANTHA/061216; Crtd /date: NAVEED/201014; Custom_Duty: 15%; Customs_HS_Code: 85332119; Distributor_name: DIGIKEY; Distributor_part_number: P0.0JCT-ND; Footprint Path: Y:\MIS_DATABASE\Library\ALTIUM_TOOL\PCB_FOOTPRINTS\Altium_Footprint_Lib.PcbLib; Height: 0.40MM; IBISSP_MODLES: VALUE REPEATING 2 TIME; Library Path: Y:\MIS_DATABASE\Library\ALTIUM_TOOL\SCHEMATICS_PARTS\MS_DISCRETE_Library.schlib; Manufacturer: PANASONIC-ECG; Mfr_name: PANASONIC-ECG; Mfr_part_number: ERJ-2GE0R00X; Mistral Part No: 110018030052-R; Package: 0402; Part_type: RESISTORS\FIXED; Project: AEGIS POM; RoHS: RoHS; Temperature: -55°C+155°C; Tolerance: NA; Voltage: NA; Wattage: 1/10W; Weight: 0.8mg; Datasheet: Y:\MIS_DATABASE\DATASHEETS\RESISTORS\PAN-ERJSER_NOV17.PDF
R568 R606 = RESISTOR: RES 0E 1/10W JUMPER 0402; Chkd/date: VASANTHA/061216; Crtd /date: NAVEED/201014; Custom_Duty: 15%; Customs_HS_Code: 85332119; Distributor_name: DIGIKEY; Distributor_part_number: P0.0JCT-ND; Footprint Path: Y:\MIS_DATABASE\Library\ALTIUM_TOOL\PCB_FOOTPRINTS\Altium_Footprint_Lib.PcbLib; Height: 0.40MM; IBISSP_MODLES: VALUE REPEATING 2 TIME; Library Path: Y:\MIS_DATABASE\Library\ALTIUM_TOOL\SCHEMATICS_PARTS\MS_DISCRETE_Library.schlib; Manufacturer: PANASONIC-ECG; Mfr_name: PANASONIC-ECG; Mfr_part_number: ERJ-2GE0R00X; Mistral Part No: 110018030052-R; Package: 0402; Part_type: RESISTORS\FIXED; Project: AEGIS POM; RoHS: RoHS; Temperature: -55°C+155°C; Tolerance: NA; Voltage: NA; Wattage: 1/10W; Weight: 0.8mg; Datasheet: Y:\MIS_DATABASE\DATASHEETS\RESISTORS\PAN-ERJSER_NOV17.PDF
SW2 = SW10_218-10LPST: SWITCH DIP SPST HALF PITCH 10POS SMD; Chkd/date: VASANTHA/250816; Crtd /date: VASANTHA/250816; Custom_Duty: 24%; Customs_HS_Code: 85369090; Distributor_name: DIGIKEY; Distributor_part_number: CT21810LPST-ND; Height: 2.65MM; Manufacturer: CTS; Mfr_name: CTS; Mistral Part No: 130016080032-R; Package: SMD; Part_type: ELECTRO-MECHANICAL\SWITCH; Project: EPOS_EVM; RoHS: RoHS; Temperature: -55°C+85°C; Tolerance: NA; Voltage: NA; Wattage: NA; Weight: NA; Datasheet: Y:\MIS_DATABASE\DATASHEETS\MISC\SWITCHES\128-12LPST.PDF
SW5 SW6 SW9 SW10 SW12 SW14 SW15 = 7914G-1-000E__7914G: SWITCH SPST-NO 4MM SQ SMD 7914G; Chkd/date: VASANTHA/271216; Crtd /date: BAVISH/051010; Custom_Duty: 24%; Customs_HS_Code: 85369090; Distributor_name: DIGIKEY; Distributor_part_number: 7914G-000ECT-ND; Height: 4.19MM; Library Ref: 7914G-1-000E _7914G; Manufacturer: BOURNS; Mfr_name: BOURNS; Mistral Part No: 130015110004-R; Package: 7914G; Part_type: ELECTRO-MECHANICAL\SWITCH; Project: AAAUC; RoHS: RoHS; Temperature: -55°C+125°C; Tolerance: NA; Voltage: NA; Wattage: NA; Weight: NA; Datasheet: Y:\MIS_DATABASE\DATASHEETS\ICS\DIGITAL\COMBINATIONAL\7914G-1-000E.PDF
U92 U102 = SN74LVC1G08DBVRE4_SOT23-5: IC SINGLE 2-INPUT POSITIVE AND GATE SOT23-5; Automotive Alternate_mfr_name: TEXAS INSTRUMENTS; Automotive Alternate_mfr_part_number: SN74LVC1G08QDBVRQ1; Chkd/date: SUHAS/221010; Crtd /date: USMAN/151008; Custom_Duty: 15%; Customs_HS_Code: 85423100; Distributor_name: DIGIKEY; Distributor_part_number: SN74LVC1G08DBVRE4-ND; Height: 1.45MM; Manufacturer: TEXAS INSTRUMENTS; Mfr_name: TEXAS INSTRUMENTS; Mistral Part No: 141009060026-R; Part_type: ICS\DIGITAL\GATES; Project: KHAN_MAIN; RoHS: Sb/ Br FREE; Temperature: -40°C+85°C; Datasheet: Y:\MIS_DATABASE\DATASHEETS\ICS\DIGITAL\GATES\SN74LVC1G08.PDF
U98 = MAX6818EAP_SSOP20: IC CMOS ESD PROTECTED SWITCH SSOP20; Chkd/date: MANIRAJA/300817; Crtd /date: MANIRAJA/300817; Custom_Duty: 15%; Customs_HS_Code: 85423100; Distributor_name: DIGIKEY; Distributor_part_number: MAX6818EAP+TCT-ND; Height: 1.99MM; Manufacturer: MAXIM; Mfr_name: MAXIM; Mistral Part No: 141017080032-R; Package: SSOP20; Part_type: ICS\INTERFACE; Project: TI_SVB_MAXWELL_DUT; RoHS: RoHS; Temperature: -40°C+125°C; Tolerance: NA; Voltage: NA; Wattage: NA; Weight: 453.6mg; Datasheet: Y:\MIS_DATABASE\DATASHEETS\ICS\MISC\MAX6816.PDF
U113 = SN74LVC2G74DCUR_VSSOP8: IC SINGLE POSITIVE-EDGE-TRIGGERED D-TYPE FLIP-FLOP VSSOP8; Chkd/date: SHREESHAIL/110106; Crtd /date: MAZHAR/110405; Custom_Duty: 15%; Customs_HS_Code: 85423100; Distributor_name: DIGIKEY; Distributor_part_number: 296-12755-1-ND; Height: 0.90MM; Manufacturer: TEXAS INSTRUMENTS; Mfr_name: TEXAS INSTRUMENTS; Mfr_part_number: SN74LVC2G74DCUR; Mistral Part No: 141009030173; Package: VSSOP8; Part_type: ICS\DIGITAL\FLIP-FLOP; Project: FPI; Datasheet: Y:\MIS_DATABASE\DATASHEETS\ICS\DIGITAL\GATES\SN74LVC2G74.PDF
U123 = TPS3808G33DBV_SOT23-6: IC 3.3V LOW QUIESCENT CURRENT PROGRAMMABLE DELAY SUPERVISORY CIRCUIT SOT23-6; Automotive Alternate_mfr_name: TEXAS INSTRUMENTS; Automotive Alternate_mfr_part_number: TPS3808G33QDBVRQ1; Chkd/date: SUHAS/050411; Crtd /date: MAZHAR/031210; Custom_Duty: 15%; Customs_HS_Code: 85423100; Distributor_name: DIGIKEY; Distributor_part_number: 296-17195-1-ND; Footprint Path: Y:\MIS_DATABASE\Library\ALTIUM_TOOL\PCB_FOOTPRINTS\Altium_Footprint_Lib.PcbLib; Height: 1.45MM; Library Path: Y:\MIS_DATABASE\Library\ALTIUM_TOOL\SCHEMATICS_PARTS\MS_MISCPOWER_Library.schlib; Manufacturer: TEXAS INSTRUMENTS; Mfr_name: TEXAS INSTRUMENTS; Mistral Part No: 142010120003-R; Package: SOT23-6; Part_type: ICS\POWER; Project: IEMS; RoHS: RoHS; Temperature: -40°C+125°C; Tolerance: NA; Voltage: NA; Wattage: NA; Weight: 36mg; Datasheet: Y:\MIS_DATABASE\DATASHEETS\ICS\POWER\TPS3808.PDF
U130 = SN74LVC1G11DCKR_SC70-6: IC SINGLE 3-INPUT POSITIVE-AND GATE SC70-6; Automotive Alternate_mfr_name: TEXAS INSTRUMENTS; Automotive Alternate_mfr_part_number: SN74LVC1G11IDCKRQ1; Chkd/date: SHREESHAIL/220506; Crtd /date: MAZHAR/150506; Custom_Duty: 15%; Customs_HS_Code: 85423100; Distributor_name: DIGIKEY; Distributor_part_number: 296-18066-1-ND; Height: 1.10MM; Manufacturer: TEXAS INSTRUMENTS; Mfr_name: TEXAS INSTRUMENTS; Mistral Part No: 141009030230-R; Part_type: ICS\DIGITAL\GATES; Project: VOCERA; RoHS: Sb/ Br FREE; Datasheet: Y:\MIS_DATABASE\DATASHEETS\ICS\DIGITAL\GATES\SN74LVC1G.PDF

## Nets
DGND: C67.2 C71.2 C72.2 C73.2 C74.1 C75.2 C78.1 C79.1 C81.1 C83.2 C85.2 C86.2 C87.1 C89.2 C90.1 C96.2 C97.2 C98.1 C99.1 C102.2 C104.2 C105.2 C109.2 C110.2 C355.2 C365.1 C372.1 C404.2 C420.1 C421.2 FL1.2(GND1) FL2.2(GND1) FL3.2(GND1) FL4.2(GND1) FL5.2(GND1) FL6.2(GND1) R32.1 R33.1 R34.1 R35.1 R36.1 R37.1 R38.1 R39.1 R40.1 R41.1 R66.2 R76.2 R114.1 R129.2 R130.2 R141.2 R539.1 R568.1 R578.2 SW5.1 SW5.4 SW6.1 SW6.4 SW9.1 SW9.4 SW10.1 SW10.4 SW12.1 SW12.4 SW14.1 SW14.4 SW15.1 SW15.4 U22.25(GND) U23.5(GND) U23.9(GND) U23.16(GND) U92.3(GND) U98.10(GND) U102.3(GND) U113.2(D) U113.4(GND) U123.2(GND) U130.2(GND) ; also on sheet 11 12 13 14 15 16 17 18 20 21 22 23 24 25 26 27 28 29 30 31 32 36 37 38 39 40 41 42 43 44 45 46 47 48 49 50 51 52 53 54 55 56 57 58 59 60 61 62 63 64 65 66 67 68 69 70 71 72 73 76 77 78 79 81 82 83 84
V3V3_REF_CDCI2: C67.1 C71.1 C81.2 FL1.3(OUT) U22.3(VDDREF)
V3V3_VCO_CDCI2: C98.2 C102.1 C104.1 FL6.3(OUT) U22.24(VDDVCO)
VDD12_CDCI2: C85.1 C86.1 C87.2 FL4.3(OUT) U22.16(VDDO12)
VDD34_CDCI2: C72.1 C73.1 C74.2 FL3.3(OUT) U22.15(VDDO34)
VDD_1V8_CDCEL: C75.1 C83.1 C89.1 FL2.3(OUT) R99.2 U23.3(VDD)
VDDOUT_1V8_CDCEL: C96.1 C97.1 C105.1 C109.1 C110.1 FL5.3(OUT) U23.6(VDDOUT) U23.10(VDDOUT) U23.13(VDDOUT)
BOARDID_EEPROM_WP: R33.2 SW2.9 ; also on sheet 30 43
CANUART_MUX_SEL0: R40.2 SW2.2 ; also on sheet 20 38
CDCEL_XIN: C78.2 U23.1(XIN/CLK) Y1.2
CDCEL_XOUT: C79.2 U23.20(XOUT) Y1.1
CDCEL_Y1: R115.1 U23.17(Y1)
CDCEL_Y4: R126.1 U23.7(Y4)
CDCEL_Y5: R131.1 U23.8(Y5)
CDCEL_Y6: R134.1 U23.12(Y6)
CDCEL_Y7: R138.1 U23.11(Y7)
CDCI2_EEPROMSEL: R135.2 R141.1 U22.23(EEPROMSEL)
CDCI2_OE1: TP24.1(TP) U22.20(STATUS/GPIO1)
CDCI2_OE4: R65.2 R66.1 TP17.1(TP) U22.11(OE/GPIO4)
CDCI2_REFSEL: R76.1 U22.4(REFSEL)
CDCI2_RSTz: R808.2 U22.8(RESETN/SYNC) ; also on sheet 38
CDCI2_XIN: C99.2 U22.1(XIN) Y3.2
CDCI2_XOUT: C90.2 U22.2(XOUT) Y3.1
CDCI2_Y0: TP18.1(TP) U22.7(Y0)
CDCI2_Y2N: R122.1 U22.17(Y2N)
CDCI2_Y2P: R123.1 U22.18(Y2P)
CSI2_REFCLK: R131.2 ; also on sheet 31
CSI_VIO_SEL: R35.2 SW2.7 ; also on sheet 31
EXP_REFCLK: R138.2 ; also on sheet 30
I2C0_SCL: U22.12(SCL/GPIO3) U23.18(S2/SCL) ; also on sheet 20 32 38 58 59
I2C0_SDA: U22.19(SDA/GPIO2) U23.19(S1/SDA) ; also on sheet 20 32 38 58 59
MAX6818_CH#: R539.2 U98.11(~{CH})
MAX6818_EN#: R568.2 U98.1(~{EN})
OSC0_REFCLK: R134.2 ; also on sheet 18
OSPI/ONAND_MUX_SEL: R41.2 SW2.1 ; also on sheet 16 18
PB_CAN_WAKEn: SW15.2 SW15.3 ; also on sheet 50 69
PB_EXTINTn: U92.1(A) U98.15(OUT5)
PB_MCU_PORz: U98.19(OUT1) ; also on sheet 36
PB_MCU_RESETz: U98.18(OUT2) ; also on sheet 36
PB_PORz: U98.17(OUT3) ; also on sheet 36
PB_RESETz: U98.16(OUT4) ; also on sheet 36
PB_SYS_IRQz: R585.2 U98.14(OUT6) U102.1(A) U123.3(~{MR})
PCIe0_4L_MODE_SEL: R37.2 SW2.5 ; also on sheet 38 59
PCIe1_2L_MODE_SEL: R36.2 SW2.6 ; also on sheet 38 60
RGMII_REFCLK: R126.2 ; also on sheet 30
SOC_EXTINTN: U92.4(Y) ; also on sheet 20
SOC_SERDES4_REFCLK_N: R122.2 R129.1 ; also on sheet 13
SOC_SERDES4_REFCLK_P: R123.2 R130.1 ; also on sheet 13
SW_PB_EXTINTn: SW6.2 SW6.3 U98.6(IN5)
SW_PB_MCU_PORz: SW14.2 SW14.3 U98.2(IN1)
SW_PB_MCU_RESETz: SW12.2 SW12.3 U98.3(IN2)
SW_PB_PORz: SW10.2 SW10.3 U98.4(IN3)
SW_PB_RESETz: SW9.2 SW9.3 U98.5(IN4)
SW_PB_SYS_IRQz: SW5.2 SW5.3 U98.7(IN6)
SYS_IRQz: U102.4(Y) ; also on sheet 18
SYS_MCU_EN: TP226.1(TP) U130.4(Y) ; also on sheet 23
SYS_MCU_PWRDN: R578.1 U113.1(CLK) ; also on sheet 18
SYS_PWR_PG: U130.6(C) ; also on sheet 36 73
TA_POWERDOWNz: R623.1 U130.3(B) ; also on sheet 47 63
TA_SOC_INT1z: U92.2(B) ; also on sheet 47 63
TA_SOC_INT2z: U102.2(B) ; also on sheet 47 63
USB1_HUB_REFCLK: R115.2 ; also on sheet 51
USBC_MODE_SEL0: R38.2 SW2.4 ; also on sheet 38 53
USBC_MODE_SEL1: R39.2 SW2.3 ; also on sheet 38 53
USER_INPUT1: R32.2 SW2.10 ; also on sheet 38
USER_LED1: LD2.1 ; also on sheet 38
USER_LED2: LD3.1 ; also on sheet 38
VSYS_3V3: C372.2 C404.1 C420.2 C421.1 R1.1 R2.1 R102.1 R585.1 R589.2 R612.2 R623.2 U98.20(VCC) U113.6(~{CLR}) U113.8(VCC) U123.5(SENSE) U123.6(VDD) U130.5(VCC) ; also on sheet 22 23 36 40 47 49 62 63 65 66 67 68 69 73 75 76 77 78 79
VSYS_IO_1V8: FL2.1(IN) FL3.1(IN) FL4.1(IN) FL5.1(IN) ; also on sheet 30 32 37 38 41 42 61 65 75
VSYS_IO_3V3: C355.1 FL1.1(IN) FL6.1(IN) R65.1 R100.1 R101.1 R103.1 R104.1 R105.1 R106.1 R107.1 R108.1 R135.1 R808.1 U92.5(VCC) ; also on sheet 18 20 22 24 29 30 31 32 36 37 38 40 41 42 43 45 46 48 50 51 53 56 57 58 59 60 61 65 66 68 75 81 82
VSYS_MCUIO_3V3: C365.2 R109.1 U102.5(VCC) ; also on sheet 16 17 18 21 22 23 36 43 44 48 49 55 62 65 68 75
VSYSMON_RESET#: R589.1 U113.7(~{PRE}) U123.1(~{RESE}T)
XDS110_BUF_SELn: R34.2 SW2.8 ; also on sheet 47
N23320850: R99.1 R114.2 U23.2(S0)
N26385797: R606.2 U113.5(Q)
N26836401: R606.1 R612.1 U130.1(A)
N26961694: R109.2 SW2.20
N26961704: R108.2 SW2.19
N26961722: R107.2 SW2.18
N26961724: R106.2 SW2.17
N26961726: R105.2 SW2.16
N26961744: R104.2 SW2.15
N26964770: R103.2 SW2.14
N26964936: R102.2 SW2.13
N26964939: R101.2 SW2.12
N26964942: R100.2 SW2.11
N27350045: LD3.2 R2.2
N27350452: LD2.2 R1.2

Not connected (* = marked no-connect by the designer): U22 5(REFP)* 6(REFN)* 9(Y4N)* 10(Y4P)* 13(Y3N)* 14(Y3P)* 21(Y1N)* 22(Y1P)*; U23 4(VCTR)* 14(Y3)* 15(Y2)*; U98 8(IN7)* 9(IN8)* 12(OUT8)* 13(OUT7)*; U113 3(~{Q})*; U123 4(CT)*

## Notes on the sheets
sheet 33
- SERDES CLOCK GENERATOR #2
- 100E
- 100MHz HCSL Clock for SOC (USB 3.1)
- REFSEL- 0 selects crystal reference
- I2C ADDRESS: 0x77
- Note: Address conflicts with CDCI Chip on Quad Port Ethernet Expansion
- Note: U3 should be in reset during programming CDCI on Quad Port Ethernet Expansion
- EEPROMSEL - LOW  - Page-0
  EEPROMSEL - HIGH - Page-1 (default)
sheet 34
- PERIPHERAL CLOCK GENERATOR
- [Bypass PLL]
- 24MHz Clock for USB HUB
- 25MHz Clock for SOC  RGMII REF CLK (GESI Board)
- 25MHz Clock for CSI2 REF CLK (CSI EXP Board)
- 26.00MHz Clock for SoC OSC0
- Note: EXP_REFCLK is Unused and can be disabled
- I2C ADDRESS: 0x6D
sheet 35
- RESET BUTTONs
- SILK: "MCU PORZ"
- SILK: "MCU WARM"
- SILK: "MAIN PORZ"
- To EXT_INTn pin on SoC
- (SOC_IRQ1#)
- From Test Automation header
- SILK: "MAIN WARM"
- SILK: "SOC_ INT1"
- (SOC_IRQ2#)
- From Test Automation header
- SILK: "SOC INT2"
- SILK: "WAKE"
- From Test automation header
- CONFIG DIP SWITCH
- Silkscreen:"USER LED2"
- Silkscreen:"CONFIG SW"
- GREEN
- GREEN
- Silkscreen:"USER LED1"
